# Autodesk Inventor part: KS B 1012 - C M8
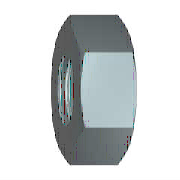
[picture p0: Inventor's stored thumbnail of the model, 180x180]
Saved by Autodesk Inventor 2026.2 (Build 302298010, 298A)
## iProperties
Created: 2025-01
Part Number: KS B 1012 - C M8
Material: 강철, 연강
Description: 6각 너트 및 6각 가는 너트
Document SubType Name: Modeling
Standard: KS B 1012
Designer: work
Standards Organization: KS
Language: ko-KR
Size Designation: C M8
Categories: <MemberInstance><Categories><Category DisplayName="조임쇠" InternalName="e4da775c-781d-43d5-af7c-5136215cf5a6" Mnemonic="FSTN"><Category DisplayName="너트" InternalN
Density: 7.85 g/cm^3
Appearance: 반연마
IsCustomPart: 1
Author: work
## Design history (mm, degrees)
body "Solid1"
workaxis "Work Axis1"
workplane "Work Plane1"
sketch "스케치1"
  geometry: L1 (-7.506, 0)-(-3.753, 6.5); L2 (-3.753, 6.5)-(3.753, 6.5); L3 (3.753, 6.5)-(7.506, 0); L4 (7.506, 0)-(3.753, -6.5); L5 (3.753, -6.5)-(-3.753, -6.5); L6 (-3.753, -6.5)-(-7.506, 0); 2 further points
  constraints: 12 end point, 1 coincident, 1 horizontal, 11 other
  dimensions: "d0" = 15.01111 distance of L3.end L1.start (= 1.1547 x SW)
extrude "본체" new body sketch "스케치1" distance "d1" = 7.9 (= KOH); taper "d2" = 0 deg
revolve "모따기1" stored, may be unused: angle "d7" = 90 deg
sketch "스케치3"
  geometry: A1 r 6.5 centre (0, 0) between (-3.25, -5.629) and (3.25, -5.629) reference; 1 further point
  constraints: 1 coincident
hole "스레드" sketch "스케치3" diameter "d25" = 6.647; stored, may be unused: countersink angle "d29" = 82 deg, drill point angle "d31" = 118 deg; dims "d26" = 6, "d27" = 4, "d28" = 2, "d30" = 8
chamfer "모따기2" distance "d8" = 0.67658 (= -0.5 x GD1 + 0.5 x NND); stored, may be unused: angle "d9" = 30 deg, second distance "d40" = 0.67658 (= -0.5 x GD1 + 0.5 x NND)
chamfer "모따기3" distance "d10" = 0.67658 (= -0.5 x GD1 + 0.5 x NND); stored, may be unused: angle "d11" = 30 deg, second distance "d41" = 0.67658 (= -0.5 x GD1 + 0.5 x NND)
sketch "스케치2"
  geometry: L1 (0, 3.753)-(0, 7.506) reference; L2 (0, 7.506)-(7.9, 7.506) reference; L3 (7.9, 3.753)-(7.9, 7.506) reference; L4 (-1.58, 0)-(9.48, 0) reference; L5 (0.581, 7.506)-(0, 6.5); L6 (7.319, 7.506)-(7.9, 6.5)
  constraints: 4 end point, 4 point on line
  dimensions: "d3" = 30 deg angle of L1 L5 (= ANG1); "d4" = 30 deg angle of L3 L6 (= ANG2); "d5" = 13 diameter of L5.end L4 (= SW0); "d6" = 13 diameter of L6.end L4 (= SW01)
other parameters: "ANG1" = 30 deg [user parameter; used in 1 equation term], "ANG2" = 30 deg [user parameter; used in 1 equation term], "NND" = 8 [user parameter; used in 4 equation terms], "KOH" = 7.9 [user parameter; used in 1 equation term], "SW" = 13 [user parameter; used in 4 equation terms], "SW0" = 13 (= SW) [user parameter; used in 1 equation term], "SW01" = 13 (= SW) [user parameter; used in 1 equation term], "GD1" = 6.64684 (computed from THREADDIA, PTC, TOA) [user parameter; used in 4 equation terms], "d13" = 0, "d14" = 0, "d39" = 0, "d42" = 0, "GUL" = 0.67658 (= 0.541266 x PTC) [user parameter], "TPU" = 8 (computed from PTC) [user parameter], "THREADDIA" = 8 [user parameter; used in 1 equation term], "TOA" = 30 deg [user parameter; used in 1 equation term], "PTC" = 1.25 [user parameter; used in 4 equation terms], "E0" = 15.015 (= 1.155 x SW) [user parameter], "GAL" = 0.67658 (= 0.541266 x PTC) [user parameter]
